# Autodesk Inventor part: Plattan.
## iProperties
Company: Autodesk EMEA
Shininess: 64.0
Length Units: 11269
Angle Units: 11279
Time Units: 11290
Mass Units: 11283
Length Display Precision: 3
Angle Display Precision: 2
Compacted: True
Part Number: Plattan.
Document SubType Name: Sheet Metal
Created: 2002-08
Designer: Franz Kaltseis
Density: 0.0
Volumn: 0.0
Area: 0.0
PropertySet Name: Model Information
Control State: 0
Master: False
Checked Out: False
Author: Franz Kaltseis
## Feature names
1. Hole1
2. Hole4
3. Hole6
4. Plate1
5. Plate2
6. Bend1
7. Plate6
8. Bend5
9. Plate7
10. Bend6
11. Plate8
12. Bend7
